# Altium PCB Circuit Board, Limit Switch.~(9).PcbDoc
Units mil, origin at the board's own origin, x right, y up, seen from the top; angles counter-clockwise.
Board outline 1122.99 x 1124 mil, 2 copper layers (Top Layer, Bottom Layer); 0 components, 2 nets, 8 pads, 0 vias.
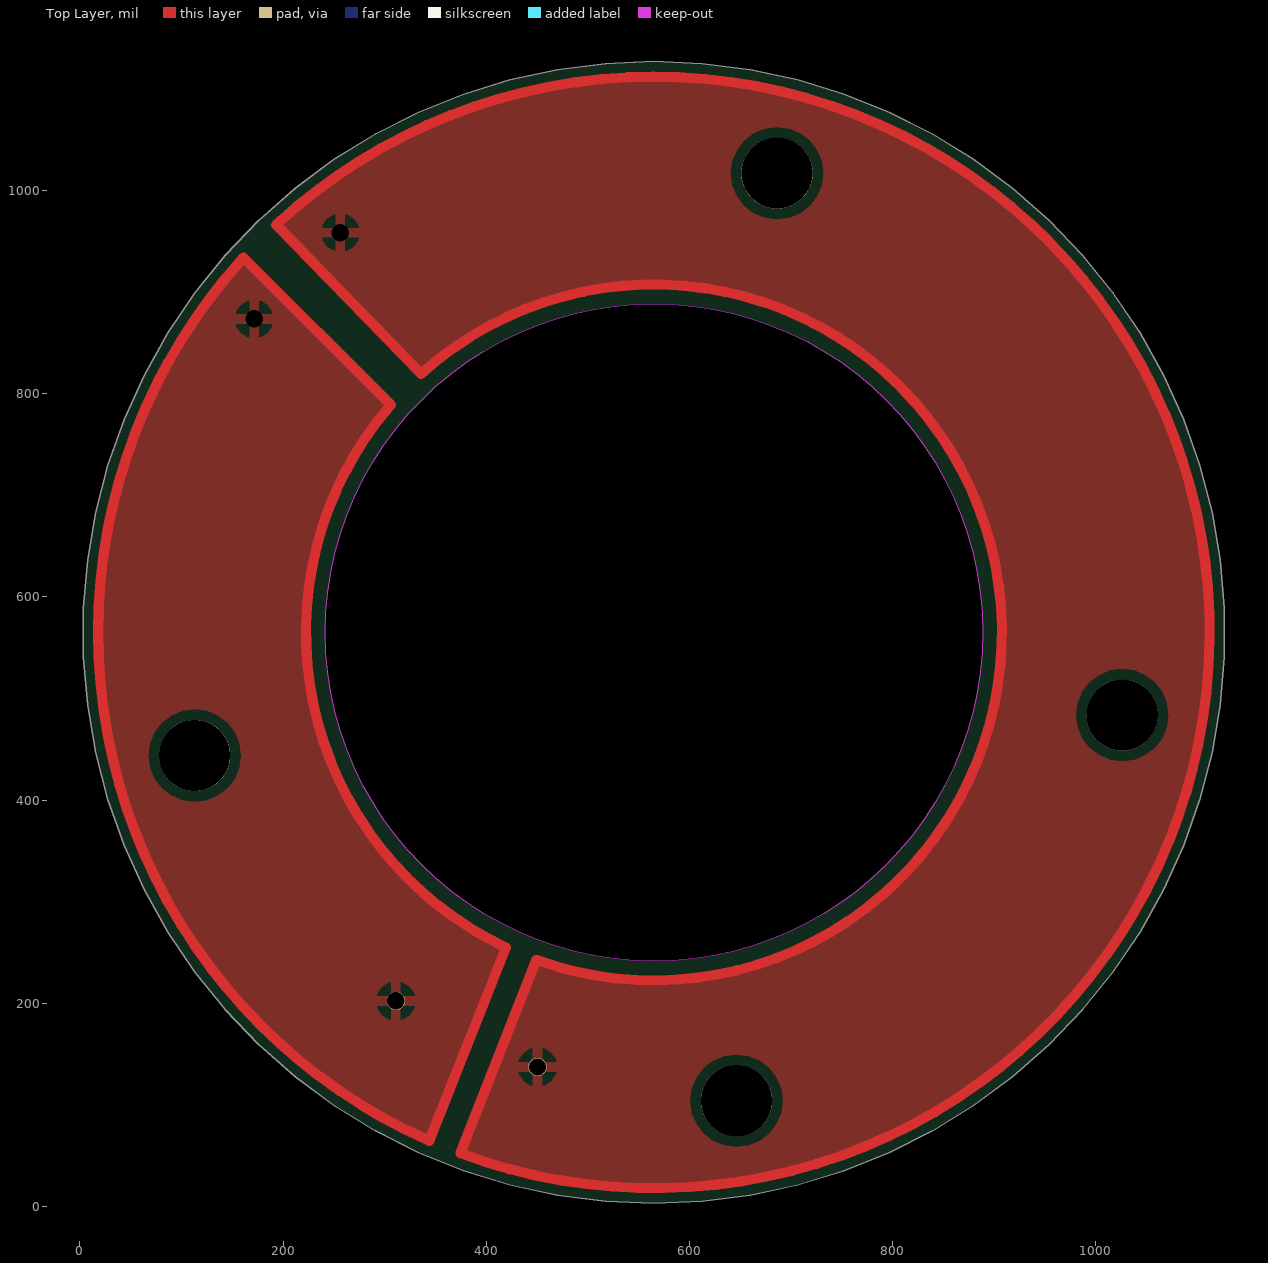
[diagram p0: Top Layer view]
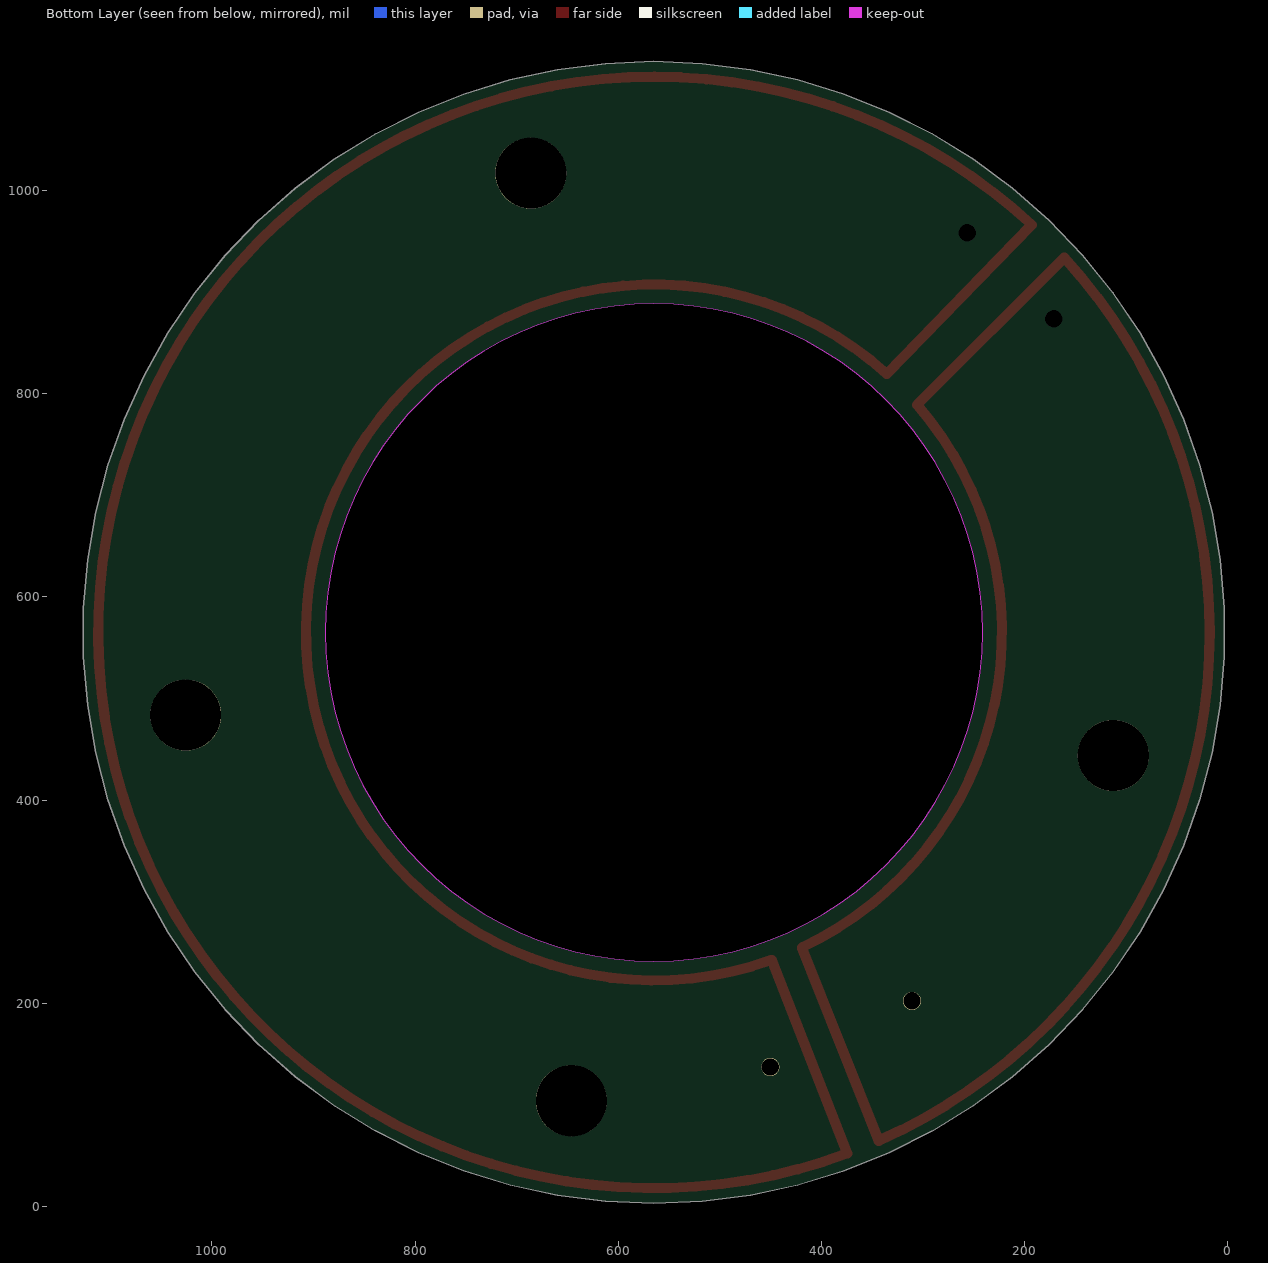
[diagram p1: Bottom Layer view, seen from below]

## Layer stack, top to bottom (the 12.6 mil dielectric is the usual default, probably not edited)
Top Layer: signal copper 1.4
Dielectric: dielectric 12.6, FR-4, Dk 4.8
Bottom Layer: signal copper 1.4

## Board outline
565,1127 517.34,1124.98 470.02,1118.92 423.39,1108.87 377.78,1094.9 333.51,1077.11 290.92,1055.63 250.29,1030.62 211.94,1002.26 176.13,970.74 143.12,936.3 113.15,899.18 86.44,859.66 63.18,818.01 43.53,774.55 27.63,729.57 15.61,683.4 7.55,636.38 3.51,588.85 3.51,541.15 7.55,493.62 15.61,446.6 27.63,400.43 43.53,355.45 63.18,311.99 86.44,270.34 113.15,230.82 143.12,193.7 176.13,159.26 211.94,127.74 250.29,99.38 290.92,74.37 333.51,52.89 377.78,35.1 423.39,21.13 470.02,11.08 517.34,5.02 565,3 612.66,5.02 659.98,11.08 706.61,21.13 752.22,35.1 796.49,52.89 839.08,74.37 879.71,99.38 918.06,127.74 953.87,159.26 986.88,193.7 1016.85,230.82 1043.56,270.34 1066.82,311.99 1086.47,355.45 1102.37,400.43 1114.39,446.6 1122.45,493.62 1126.49,541.15 1126.49,588.85 1122.45,636.38 1114.39,683.4 1102.37,729.57 1086.47,774.55 1066.82,818.01 1043.56,859.66 1016.85,899.18 986.88,936.3 953.87,970.74 918.06,1002.26 879.71,1030.62 839.08,1055.63 796.49,1077.11 752.22,1094.9 706.61,1108.87 659.98,1118.92 612.66,1124.98
cut-out: 565,241.5 cw(c565,565) 241.5,565 cw(c565,565) 565,888.5 cw(c565,565) 888.5,565 cw(c565,565)

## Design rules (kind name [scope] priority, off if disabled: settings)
Clearance [All] p1: gap=10
PolygonConnect [All] p1: connectstyle=Relief reliefconductorwidth=10 reliefentries=4 polygonreliefangle="90 Angle"
RoutingVias [All] p1: holewidth=28 width=50 viastyle="Through Hole" minholewidth=28 minwidth=50 maxholewidth=28 maxwidth=50
SilkscreenOverComponentPads [All] p1: minsilkscreentomaskgap=10
SolderMaskExpansion [All] p1: expansion=4
Width [All] p1: maxlimit=10 minlimit=10 preferedwidth=10
27 further rules are at their usual default settings.

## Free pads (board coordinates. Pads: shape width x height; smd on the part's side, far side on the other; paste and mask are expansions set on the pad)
  round 70 hole 70 unplated: 1(112.95,443.87)
  round 16.1 hole 17.1: 1(171.57,873.57) 1(256.43,958.42)
  round 18 hole 17.1: 1(311.05,202.32) 1(450.41,137.34)
  round 70 hole 70: 1(646.27,104.11) 1(686.13,1017.05) 1(1025.89,483.73)

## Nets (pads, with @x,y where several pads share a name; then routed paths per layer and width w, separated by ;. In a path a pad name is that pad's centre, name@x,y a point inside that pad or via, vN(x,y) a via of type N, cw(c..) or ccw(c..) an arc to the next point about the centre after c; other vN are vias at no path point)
SW1: pad.1@171.57,873.57 pad.1@311.05,202.32 | length 2076.2
  Top Layer w10: 161.11,933.89 306,789 ; 161.16,933.94 ccw(c565,565) 343.95,64.66 ; 305.26,788.25 ccw(c565,565) 418.57,255.38 ; 343.77,64.72 419.39,255.05
SW2: pad.1@256.43,958.42 pad.1@450.41,137.34 | length 4175.3
  Top Layer w10: 193.12,966.14 cw(c565,565) 374.55,52.23 449.1,242.72 ; 193.14,966.16 335.79,819.47 ; 336.26,819.92 cw(c565,565) 449.6,242.53

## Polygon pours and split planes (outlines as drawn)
SW2 on Top Layer "Top Layer-No Net" (solid, pour order 29): 374.55,52.23 ccw(c565,565) 193.12,966.14 193.14,966.16 335.79,819.47 336.26,819.92 cw(c565,565) 449.6,242.53 449.1,242.72
SW1 on Top Layer "Top Layer-No Net" (solid, pour order 27): 343.95,64.66 cw(c565,565) 161.16,933.94 161.11,933.89 308.82,786.18 308.29,785.64 ccw(c565,565) 420.28,259 420.87,258.76

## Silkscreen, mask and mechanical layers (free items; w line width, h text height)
Mechanical 1:
  circle w10: c565,565 r323.5
  circle w10: c565,565 r562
